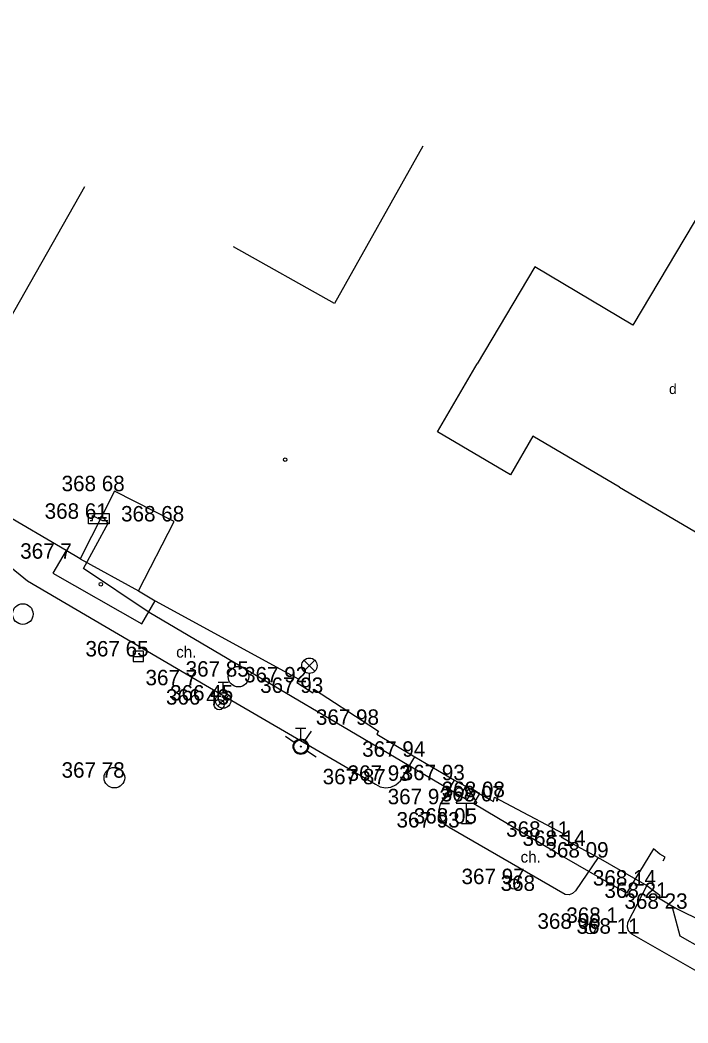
# Model space of a CAD drawing. Extents: x -688316 to -688024, y -973785 to -973591.
# Drawn here: x -688157.86 to -688125.39, y -973639.59 to -973590.87 of the extents above; entities that cross this region are included whole.
import ezdxf

# ---------------------------------------------------------------- set-up
doc = ezdxf.new("R2010")
doc.units = 0
for name, color, linetype in [('Vrstva 10', 7, 'Continuous'), ('Vrstva 1_elektro CEZ', 7, 'Continuous'), ('Vrstva 24', 7, 'Continuous'), ('Vrstva 27', 7, 'Continuous'), ('Vrstva 28_Verejne osvetleni', 7, 'Continuous'), ('Vrstva 3', 7, 'Continuous'), ('Vrstva 33', 7, 'Continuous'), ('Vrstva 34', 7, 'Continuous'), ('Vrstva 36', 7, 'Continuous'), ('Vrstva 40', 7, 'Continuous'), ('Vrstva 5', 7, 'Continuous'), ('Vrstva 58', 7, 'Continuous'), ('Vrstva 6', 7, 'Continuous'), ('Vrstva 9', 7, 'Continuous')]:
    doc.layers.add(name, color=color, linetype=linetype)

# ---------------------------------------------------------------- blocks, each defined once
blk = doc.blocks.new('B_NESP')
at = {"layer": 'Vrstva 58'}
blk.add_circle((0, 0), 0.875, dxfattribs=at)
blk = doc.blocks.new('DZ')
at = {"layer": 'Vrstva 34'}
for p, q in [((-5, 10), (0, 18.5)), ((0, 18.5), (5, 10)), ((-5, 10), (5, 10)), ((0, 0), (0, 10)), ((-2.49, 0), (2.49, 0))]:
    blk.add_line(p, q, dxfattribs=at)
blk = doc.blocks.new('LAO')
at = {"layer": 'Vrstva 33'}
for p, q in [((-2.65, 14.16), (2.65, 8.85)), ((-2.65, 8.85), (2.65, 14.16)), ((0, 0), (0, 7.75))]:
    blk.add_line(p, q, dxfattribs=at)
blk.add_circle((0, 11.5), 3.75, dxfattribs=at)
blk = doc.blocks.new('HYP')
at = {"layer": 'Vrstva 28_Verejne osvetleni'}
for p, q in [((-2.5, 8.99), (2.5, 8.99)), ((0, 3.75), (0, 8.99)), ((-2.65, -2.65), (2.65, 2.65))]:
    blk.add_line(p, q, dxfattribs=at)
blk.add_circle((0, 0), 3.75, dxfattribs=at)
blk = doc.blocks.new('SV')
at = {"layer": 'Vrstva 28_Verejne osvetleni'}
blk.add_circle((0, 0), 2.5, dxfattribs=at)
blk = doc.blocks.new('SAK')
at = {"layer": 'Vrstva 27'}
blk.add_circle((0, 0), 5, dxfattribs=at)
blk = doc.blocks.new('VP')
at = {"layer": 'Vrstva 27'}
blk.add_line((-2.5, 0), (2.5, 0), dxfattribs=at)
blk.add_lwpolyline([(-2.5, -2.5), (2.5, -2.5), (2.5, 2.5), (-2.5, 2.5)], close=True, dxfattribs=at)
blk = doc.blocks.new('PE')
at = {"layer": 'Vrstva 24'}
for p, q in [((-5, 2.5), (5, 2.5)), ((-5, -2.5), (-5, 2.5)), ((-3.11, 1.66), (1.89, -0.84)), ((-3.11, -0.84), (-3.11, 1.66)), ((5, 2.5), (5, -2.5)), ((5, -2.5), (-5, -2.5)), ((-4.21, -0.84), (-3.11, -0.84)), ((1.89, -0.84), (4.34, -0.84))]:
    blk.add_line(p, q, dxfattribs=at)
blk = doc.blocks.new('HYN')
at = {"layer": 'Vrstva 28_Verejne osvetleni'}
for p, q in [((-2.5, 8.99), (2.5, 8.99)), ((0, 3.75), (0, 8.99))]:
    blk.add_line(p, q, dxfattribs=at)
blk.add_circle((0, 0), 3.75, dxfattribs=at)
blk = doc.blocks.new('DKCH0')
at = {"layer": 'Vrstva 40'}
blk.add_text('ch.', height=5.5, dxfattribs=at).set_placement((-6.26, -3.04))
blk = doc.blocks.new('DVUR')
at = {"layer": 'Vrstva 36'}
blk.add_text('d', height=5, dxfattribs=at).set_placement((-1.69, -2.5))
blk = doc.blocks.new('HYD_12')
at = {"layer": 'Vrstva 9'}
for p, q in [((-0.01, 13.21), (0.1, 4.84)), ((4.84, 0), (13.21, 0.01)), ((-13.17, -0.02), (-4.83, -0.01))]:
    blk.add_line(p, q, dxfattribs=at)
for radius in [4.84, 4.84, 0.333, 0.333]:
    blk.add_circle((0, 0), radius, dxfattribs=at)

msp = doc.modelspace()

# ---------------------------------------------------------------- linework, layer by layer
at = {"layer": 'Vrstva 10'}
for p, q in [((-688157.5, -973618.12), (-688148.84, -973623.19)), ((-688148.84, -973623.19), (-688140.58, -973628)), ((-688131.36, -973633.35), (-688136.99, -973630.1)), ((-688128.13, -973635.26), (-688116.85, -973641.76))]:
    msp.add_line(p, q, dxfattribs=at)
for points in [[(-688158.71, -973614.82), (-688158.99, -973615.37), (-688158.98, -973616.01), (-688158.98, -973616.28), (-688158.46, -973617.32), (-688157.5, -973618.12)], [(-688140.58, -973628), (-688140.35, -973628.12), (-688140.09, -973628.17), (-688139.83, -973628.14), (-688139.59, -973628.03), (-688139.37, -973627.83), (-688138.66, -973626.66)], [(-688136.99, -973630.1), (-688137.2, -973629.95), (-688137.37, -973629.75), (-688137.46, -973629.5), (-688137.48, -973629.23), (-688137.42, -973628.97), (-688136.74, -973627.8)], [(-688129.75, -973631.56), (-688130.86, -973633.18), (-688131, -973633.31), (-688131.17, -973633.37), (-688131.36, -973633.35)], [(-688127.39, -973632.92), (-688128.33, -973634.73), (-688128.35, -973634.92), (-688128.29, -973635.1), (-688128.13, -973635.26)]]:
    msp.add_lwpolyline(points, dxfattribs=at)
at = {"layer": 'Vrstva 1_elektro CEZ'}
for points in [[(-688135.678, -973628.352), (-688135.851, -973628.251), (-688136.145, -973628.753), (-688151.573, -973619.651), (-688154.772, -973617.522), (-688153.566, -973615.31), (-688153.883, -973614.965), (-688154.03, -973615.1)], [(-688126.6, -973631.713), (-688126.498, -973631.541), (-688126.75, -973631.392), (-688127.068, -973631.135), (-688128.38, -973633.294), (-688131.918, -973631.246), (-688135.8, -973628.956), (-688135.506, -973628.453), (-688135.678, -973628.352)]]:
    msp.add_lwpolyline(points, dxfattribs=at)
at = {"layer": 'Vrstva 5'}
for p, q in [((-688119.25, -973590.87), (-688128.07, -973605.69)), ((-688154.72, -973598.97), (-688160.75, -973609.55)), ((-688132.84, -973602.86), (-688135.63, -973607.58)), ((-688128.07, -973605.69), (-688132.84, -973602.86)), ((-688128.71, -973613.57), (-688122.97, -973616.95)), ((-688130.81, -973630.99), (-688129.75, -973631.56))]:
    msp.add_line(p, q, dxfattribs=at)
for points in [[(-688138.28, -973597), (-688142.57, -973604.64), (-688147.48, -973601.89)], [(-688128.71, -973613.57), (-688132.93, -973611.09), (-688134.02, -973612.96), (-688137.57, -973610.88), (-688135.63, -973607.58)], [(-688154.93, -973617.04), (-688155.61, -973616.64), (-688158.71, -973614.82), (-688162.47, -973612.61)], [(-688152.1, -973618.6), (-688150.37, -973615.23), (-688153.26, -973613.76), (-688154.93, -973617.04)], [(-688155.61, -973616.64), (-688156.26, -973617.74), (-688151.93, -973620.2), (-688151.28, -973619.09)], [(-688152.1, -973618.6), (-688151.28, -973619.09), (-688144.3, -973622.89), (-688144.4, -973623.05), (-688143.62, -973623.56), (-688143.54, -973623.39), (-688140.91, -973625.11), (-688140.43, -973625.42), (-688140.52, -973625.57), (-688138.66, -973626.66)], [(-688148.18, -973624.13), (-688147.98, -973623.93)], [(-688136.74, -973627.8), (-688134.84, -973628.83), (-688134.79, -973628.62), (-688131.46, -973630.39), (-688131.55, -973630.55), (-688130.92, -973630.93), (-688130.81, -973630.99)], [(-688127.39, -973632.92), (-688126.75, -973633.39), (-688126.83, -973633.52), (-688126.17, -973633.9), (-688125.91, -973634.05), (-688122.3, -973635.83), (-688122.45, -973636.07), (-688122.11, -973636.25), (-688121.52, -973636.59), (-688121.44, -973636.46), (-688120.76, -973636.84), (-688118.29, -973638.05), (-688118.38, -973638.25), (-688117.46, -973638.76), (-688117.34, -973639), (-688116.87, -973639.22), (-688116.45, -973639.15), (-688114.55, -973640.02), (-688114.81, -973640.46), (-688114.6, -973640.52), (-688114.18, -973640.39)], [(-688126.17, -973633.9), (-688125.79, -973635.37), (-688123.61, -973636.6), (-688122.11, -973636.25)]]:
    msp.add_lwpolyline(points, dxfattribs=at)
at = {"layer": 'Vrstva 6'}
for p, q in [((-688154.93, -973617.04), (-688152.1, -973618.6)), ((-688138.66, -973626.66), (-688136.74, -973627.8)), ((-688129.75, -973631.56), (-688127.39, -973632.92))]:
    msp.add_line(p, q, dxfattribs=at)

# ---------------------------------------------------------------- block references
at = {"layer": 'Vrstva 24', "xscale": 0.1, "yscale": 0.10000000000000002}
msp.add_blockref('PE', (-688154.03, -973615.1), dxfattribs=at)
at = {"layer": 'Vrstva 27', "xscale": 0.1, "yscale": 0.10000000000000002}
for name, p in [('SAK', (-688157.72, -973619.73)), ('VP', (-688152.1, -973621.79)), ('SAK', (-688147.24, -973622.77)), ('SAK', (-688153.27, -973627.68))]:
    msp.add_blockref(name, p, dxfattribs=at)
at = {"layer": 'Vrstva 28_Verejne osvetleni', "xscale": 0.1, "yscale": 0.10000000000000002}
for name, p in [('HYP', (-688147.98, -973623.93)), ('SV', (-688148.18, -973624.13)), ('HYN', (-688144.21, -973626.17)), ('SV', (-688133.83, -973632.85)), ('SV', (-688130.14, -973635.02))]:
    msp.add_blockref(name, p, dxfattribs=at)
at = {"layer": 'Vrstva 33', "xscale": 0.1, "yscale": 0.10000000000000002}
msp.add_blockref('LAO', (-688143.79, -973623.39), dxfattribs=at)
at = {"layer": 'Vrstva 34', "xscale": 0.1, "yscale": 0.10000000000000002}
msp.add_blockref('DZ', (-688136.15, -973629.91), dxfattribs=at)
msp.add_blockref('DZ', (-688136.15, -973629.91), dxfattribs=at)
msp.add_blockref('DZ', (-688136.15, -973629.91), dxfattribs=at)
msp.add_blockref('DZ', (-688136.15, -973629.91), dxfattribs=at)
at = {"layer": 'Vrstva 36', "xscale": 0.1, "yscale": 0.10000000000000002}
msp.add_blockref('DVUR', (-688126.14, -973608.79), dxfattribs=at)
at = {"layer": 'Vrstva 40', "xscale": 0.1, "yscale": 0.10000000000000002}
for p in [(-688149.64, -973621.54), (-688132.9, -973631.5)]:
    msp.add_blockref('DKCH0', p, dxfattribs=at)
at = {"layer": 'Vrstva 58', "xscale": 0.1, "yscale": 0.10000000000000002}
for p in [(-688144.97, -973612.23), (-688144.97, -973612.23), (-688144.97, -973612.23), (-688144.97, -973612.23), (-688153.93, -973618.28), (-688153.93, -973618.28), (-688153.93, -973618.28), (-688153.93, -973618.28)]:
    msp.add_blockref('B_NESP', p, dxfattribs=at)
at = {"layer": 'Vrstva 9', "xscale": 0.06839988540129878, "yscale": 0.06839988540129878, "rotation": -33.801497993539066}
msp.add_blockref('HYD_12', (-688144.211, -973626.167), dxfattribs=at)

# ---------------------------------------------------------------- texts
at = {"layer": 'Vrstva 3'}
for s, p in [('368 68 ', (-688155.835, -973613.76)), ('368 68 ', (-688155.835, -973613.76)), ('368 68 ', (-688155.835, -973613.76)), ('368 68 ', (-688155.835, -973613.76)), ('368 68 ', (-688155.835, -973613.76)), ('368 68 ', (-688155.835, -973613.76)), ('368 68 ', (-688155.835, -973613.76)), ('368 61 ', (-688156.66, -973615.1)), ('368 61 ', (-688156.66, -973615.1)), ('368 61 ', (-688156.66, -973615.1)), ('368 61 ', (-688156.66, -973615.1)), ('368 61 ', (-688156.66, -973615.1)), ('368 61 ', (-688156.66, -973615.1)), ('368 61 ', (-688156.66, -973615.1)), ('368 68 ', (-688152.945, -973615.23)), ('368 68 ', (-688152.945, -973615.23)), ('368 68 ', (-688152.945, -973615.23)), ('368 68 ', (-688152.945, -973615.23)), ('368 68 ', (-688152.945, -973615.23)), ('368 68 ', (-688152.945, -973615.23)), ('368 68 ', (-688152.945, -973615.23)), ('367 7  ', (-688157.847, -973617.04)), ('367 7  ', (-688157.847, -973617.04)), ('367 7  ', (-688157.847, -973617.04)), ('367 7  ', (-688157.847, -973617.04)), ('367 7  ', (-688157.847, -973617.04)), ('367 7  ', (-688157.847, -973617.04)), ('367 7  ', (-688157.847, -973617.04)), ('367 65 ', (-688154.675, -973621.79)), ('367 65 ', (-688154.675, -973621.79)), ('367 65 ', (-688154.675, -973621.79)), ('367 65 ', (-688154.675, -973621.79)), ('367 65 ', (-688154.675, -973621.79)), ('367 65 ', (-688154.675, -973621.79)), ('367 65 ', (-688154.675, -973621.79)), ('367 85 ', (-688149.806, -973622.77)), ('367 85 ', (-688149.806, -973622.77)), ('367 85 ', (-688149.806, -973622.77)), ('367 85 ', (-688149.806, -973622.77)), ('367 85 ', (-688149.806, -973622.77)), ('367 85 ', (-688149.806, -973622.77)), ('367 85 ', (-688149.806, -973622.77)), ('367 7  ', (-688151.757, -973623.19)), ('367 7  ', (-688151.757, -973623.19)), ('367 7  ', (-688151.757, -973623.19)), ('367 7  ', (-688151.757, -973623.19)), ('367 7  ', (-688151.757, -973623.19)), ('367 7  ', (-688151.757, -973623.19)), ('367 7  ', (-688151.757, -973623.19)), ('367 92 ', (-688146.966, -973623.05)), ('367 92 ', (-688146.966, -973623.05)), ('367 92 ', (-688146.966, -973623.05)), ('367 92 ', (-688146.966, -973623.05)), ('367 92 ', (-688146.966, -973623.05)), ('367 92 ', (-688146.966, -973623.05)), ('367 92 ', (-688146.966, -973623.05)), ('367 93 ', (-688146.186, -973623.56)), ('367 93 ', (-688146.186, -973623.56)), ('367 93 ', (-688146.186, -973623.56)), ('367 93 ', (-688146.186, -973623.56)), ('367 93 ', (-688146.186, -973623.56)), ('367 93 ', (-688146.186, -973623.56)), ('367 93 ', (-688146.186, -973623.56)), ('366 43 ', (-688150.763, -973624.13)), ('366 43 ', (-688150.763, -973624.13)), ('366 43 ', (-688150.763, -973624.13)), ('366 43 ', (-688150.763, -973624.13)), ('366 43 ', (-688150.763, -973624.13)), ('366 43 ', (-688150.763, -973624.13)), ('366 43 ', (-688150.763, -973624.13)), ('366 45 ', (-688150.563, -973623.93)), ('366 45 ', (-688150.563, -973623.93)), ('366 45 ', (-688150.563, -973623.93)), ('366 45 ', (-688150.563, -973623.93)), ('366 45 ', (-688150.563, -973623.93)), ('366 45 ', (-688150.563, -973623.93)), ('366 45 ', (-688150.563, -973623.93)), ('367 98 ', (-688143.476, -973625.11)), ('367 98 ', (-688143.476, -973625.11)), ('367 98 ', (-688143.476, -973625.11)), ('367 98 ', (-688143.476, -973625.11)), ('367 98 ', (-688143.476, -973625.11)), ('367 98 ', (-688143.476, -973625.11)), ('367 98 ', (-688143.476, -973625.11)), ('367 94 ', (-688141.226, -973626.66)), ('367 94 ', (-688141.226, -973626.66)), ('367 94 ', (-688141.226, -973626.66)), ('367 94 ', (-688141.226, -973626.66)), ('367 94 ', (-688141.226, -973626.66)), ('367 94 ', (-688141.226, -973626.66)), ('367 94 ', (-688141.226, -973626.66)), ('367 78 ', (-688155.836, -973627.68)), ('367 78 ', (-688155.836, -973627.68)), ('367 78 ', (-688155.836, -973627.68)), ('367 78 ', (-688155.836, -973627.68)), ('367 78 ', (-688155.836, -973627.68)), ('367 78 ', (-688155.836, -973627.68)), ('367 78 ', (-688155.836, -973627.68)), ('367 87 ', (-688143.146, -973628)), ('367 87 ', (-688143.146, -973628)), ('367 87 ', (-688143.146, -973628)), ('367 87 ', (-688143.146, -973628)), ('367 87 ', (-688143.146, -973628)), ('367 87 ', (-688143.146, -973628)), ('367 87 ', (-688143.146, -973628)), ('367 93 ', (-688141.936, -973627.83)), ('367 93 ', (-688141.936, -973627.83)), ('367 93 ', (-688141.936, -973627.83)), ('367 93 ', (-688141.936, -973627.83)), ('367 93 ', (-688141.936, -973627.83)), ('367 93 ', (-688141.936, -973627.83)), ('367 93 ', (-688141.936, -973627.83)), ('367 93 ', (-688139.306, -973627.8)), ('367 93 ', (-688139.306, -973627.8)), ('367 93 ', (-688139.306, -973627.8)), ('367 93 ', (-688139.306, -973627.8)), ('367 93 ', (-688139.306, -973627.8)), ('367 93 ', (-688139.306, -973627.8)), ('367 93 ', (-688139.306, -973627.8)), ('368 08 ', (-688137.356, -973628.62)), ('368 08 ', (-688137.356, -973628.62)), ('368 08 ', (-688137.356, -973628.62)), ('368 08 ', (-688137.356, -973628.62)), ('368 08 ', (-688137.356, -973628.62)), ('368 08 ', (-688137.356, -973628.62)), ('368 08 ', (-688137.356, -973628.62)), ('367 92 ', (-688139.986, -973628.97)), ('367 92 ', (-688139.986, -973628.97)), ('367 92 ', (-688139.986, -973628.97)), ('367 92 ', (-688139.986, -973628.97)), ('367 92 ', (-688139.986, -973628.97)), ('367 92 ', (-688139.986, -973628.97)), ('367 92 ', (-688139.986, -973628.97)), ('368 07 ', (-688137.406, -973628.83)), ('368 07 ', (-688137.406, -973628.83)), ('368 07 ', (-688137.406, -973628.83)), ('368 07 ', (-688137.406, -973628.83)), ('368 07 ', (-688137.406, -973628.83)), ('368 07 ', (-688137.406, -973628.83)), ('368 07 ', (-688137.406, -973628.83)), ('368 05 ', (-688138.716, -973629.91)), ('368 05 ', (-688138.716, -973629.91)), ('368 05 ', (-688138.716, -973629.91)), ('368 05 ', (-688138.716, -973629.91)), ('368 05 ', (-688138.716, -973629.91)), ('368 05 ', (-688138.716, -973629.91)), ('368 05 ', (-688138.716, -973629.91)), ('367 93 ', (-688139.556, -973630.1)), ('367 93 ', (-688139.556, -973630.1)), ('367 93 ', (-688139.556, -973630.1)), ('367 93 ', (-688139.556, -973630.1)), ('367 93 ', (-688139.556, -973630.1)), ('367 93 ', (-688139.556, -973630.1)), ('367 93 ', (-688139.556, -973630.1)), ('368 11 ', (-688134.227, -973630.55)), ('368 11 ', (-688134.227, -973630.55)), ('368 11 ', (-688134.227, -973630.55)), ('368 11 ', (-688134.227, -973630.55)), ('368 11 ', (-688134.227, -973630.55)), ('368 11 ', (-688134.227, -973630.55)), ('368 11 ', (-688134.227, -973630.55)), ('368 14 ', (-688133.431, -973630.99)), ('368 14 ', (-688133.431, -973630.99)), ('368 14 ', (-688133.431, -973630.99)), ('368 14 ', (-688133.431, -973630.99)), ('368 14 ', (-688133.431, -973630.99)), ('368 14 ', (-688133.431, -973630.99)), ('368 14 ', (-688133.431, -973630.99)), ('368 09 ', (-688132.316, -973631.56)), ('368 09 ', (-688132.316, -973631.56)), ('368 09 ', (-688132.316, -973631.56)), ('368 09 ', (-688132.316, -973631.56)), ('368 09 ', (-688132.316, -973631.56)), ('368 09 ', (-688132.316, -973631.56)), ('368 09 ', (-688132.316, -973631.56)), ('367 97 ', (-688136.396, -973632.85)), ('367 97 ', (-688136.396, -973632.85)), ('367 97 ', (-688136.396, -973632.85)), ('367 97 ', (-688136.396, -973632.85)), ('367 97 ', (-688136.396, -973632.85)), ('367 97 ', (-688136.396, -973632.85)), ('367 97 ', (-688136.396, -973632.85)), ('368 14 ', (-688130.011, -973632.92)), ('368 14 ', (-688130.011, -973632.92)), ('368 14 ', (-688130.011, -973632.92)), ('368 14 ', (-688130.011, -973632.92)), ('368 14 ', (-688130.011, -973632.92)), ('368 14 ', (-688130.011, -973632.92)), ('368 14 ', (-688130.011, -973632.92)), ('368    ', (-688134.497, -973633.18)), ('368    ', (-688134.497, -973633.18)), ('368    ', (-688134.497, -973633.18)), ('368    ', (-688134.497, -973633.18)), ('368    ', (-688134.497, -973633.18)), ('368    ', (-688134.497, -973633.18)), ('368    ', (-688134.497, -973633.18)), ('368 21 ', (-688129.451, -973633.52)), ('368 21 ', (-688129.451, -973633.52)), ('368 21 ', (-688129.451, -973633.52)), ('368 21 ', (-688129.451, -973633.52)), ('368 21 ', (-688129.451, -973633.52)), ('368 21 ', (-688129.451, -973633.52)), ('368 21 ', (-688129.451, -973633.52)), ('368 23 ', (-688128.476, -973634.05)), ('368 23 ', (-688128.476, -973634.05)), ('368 23 ', (-688128.476, -973634.05)), ('368 23 ', (-688128.476, -973634.05)), ('368 23 ', (-688128.476, -973634.05)), ('368 23 ', (-688128.476, -973634.05)), ('368 23 ', (-688128.476, -973634.05)), ('368 1  ', (-688131.303, -973634.73)), ('368 1  ', (-688131.303, -973634.73)), ('368 1  ', (-688131.303, -973634.73)), ('368 1  ', (-688131.303, -973634.73)), ('368 1  ', (-688131.303, -973634.73)), ('368 1  ', (-688131.303, -973634.73)), ('368 1  ', (-688131.303, -973634.73)), ('368 06 ', (-688132.706, -973635.02)), ('368 06 ', (-688132.706, -973635.02)), ('368 06 ', (-688132.706, -973635.02)), ('368 06 ', (-688132.706, -973635.02)), ('368 06 ', (-688132.706, -973635.02)), ('368 06 ', (-688132.706, -973635.02)), ('368 06 ', (-688132.706, -973635.02)), ('368 11 ', (-688130.807, -973635.26)), ('368 11 ', (-688130.807, -973635.26)), ('368 11 ', (-688130.807, -973635.26)), ('368 11 ', (-688130.807, -973635.26)), ('368 11 ', (-688130.807, -973635.26)), ('368 11 ', (-688130.807, -973635.26)), ('368 11 ', (-688130.807, -973635.26))]:
    msp.add_text(s, height=0.75, dxfattribs=at).set_placement(p)

doc.saveas('drawing.dxf')
